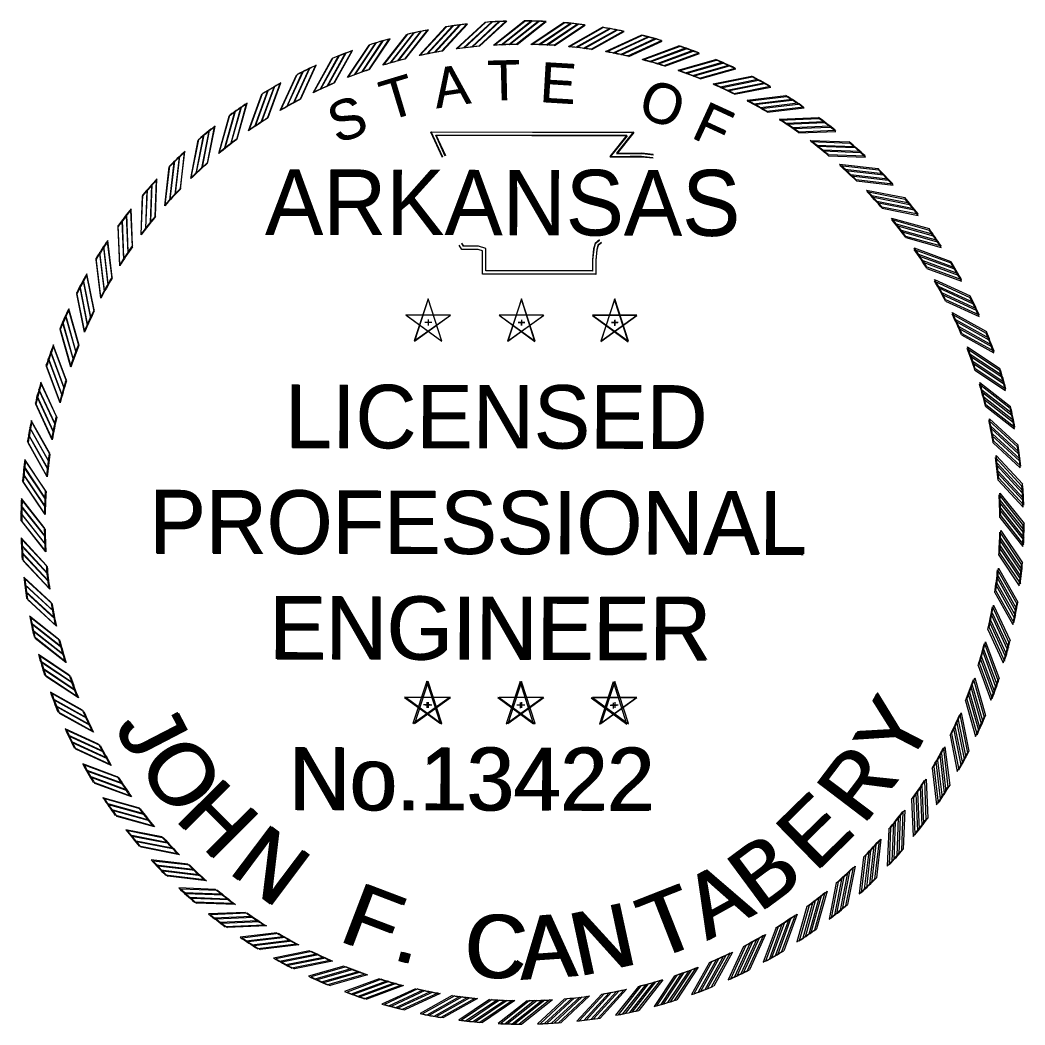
# Model space of a CAD drawing. Extents: x 1448008.9 to 1448047, y 2057056.5 to 2057079.8.
# Drawn here: x 1448044.528 to 1448046.959, y 2057073.225 to 2057075.654 of the extents above; entities that cross this region are included whole.
import ezdxf

# ---------------------------------------------------------------- set-up
doc = ezdxf.new("R2010")
doc.units = 0
doc.layers.add('Default', color=7, linetype='Continuous')

# ---------------------------------------------------------------- blocks, each defined once
blk = doc.blocks.new('STAR')
at = {"layer": 'Default'}
for p, q in [((-0.0001, 0.0615), (-0.0366, -0.0504)), ((0.0362, -0.0503), (0, 0.0617)), ((0.0587, 0.0188), (-0.059, 0.0189)), ((-0.0589, 0.0188), (0.0363, -0.0505)), ((-0.0365, -0.0503), (0.0589, 0.0188)), ((-0.0085, 0), (0.009, 0)), ((0, 0.0063), (0, -0.0085))]:
    blk.add_line(p, q, dxfattribs=at)
blk = doc.blocks.new('RP')
at = {"layer": 'Default'}
for p, q in [((-0.0781, 1.2656), (0.003, 1.33)), ((-0.058, 1.2667), (0.0216, 1.3299)), ((-0.0375, 1.2674), (0.0405, 1.3294)), ((-0.0176, 1.2679), (0.059, 1.3287))]:
    blk.add_line(p, q, dxfattribs=at)
for radius, start, end in [(1.33, 87.4562, 89.8699), (1.268, 90.7933, 93.5307)]:
    blk.add_arc((0, 0), radius, start, end, dxfattribs=at)

msp = doc.modelspace()

# ---------------------------------------------------------------- linework, layer by layer
at = {"layer": 'Default'}
for points in [[(1448045.5496, 2057075.322), (1448045.5213, 2057075.3834), (1448046.0117, 2057075.3837), (1448045.9707, 2057075.3322), (1448046.004, 2057075.3327), (1448046.0319, 2057075.333), (1448046.0597, 2057075.33)], [(1448045.5506, 2057075.3224), (1448045.5225, 2057075.3839), (1448046.0129, 2057075.3825), (1448045.9717, 2057075.3311), (1448046.005, 2057075.3314), (1448046.0329, 2057075.3317), (1448046.0607, 2057075.3286)], [(1448045.5567, 2057075.3253), (1448045.5334, 2057075.3757), (1448045.9956, 2057075.3759), (1448045.9544, 2057075.3243), (1448046.0041, 2057075.3249), (1448046.0315, 2057075.3253), (1448046.0588, 2057075.3223)], [(1448045.5576, 2057075.3256), (1448045.5346, 2057075.3761), (1448045.9967, 2057075.3747), (1448045.9554, 2057075.3232), (1448046.0051, 2057075.3237), (1448046.0325, 2057075.3239), (1448046.0598, 2057075.3209)], [(1448045.9295, 2057075.1226), (1448045.9192, 2057075.1142), (1448045.9156, 2057075.101), (1448045.9127, 2057075.0746), (1448045.9127, 2057075.048), (1448045.6545, 2057075.048), (1448045.6545, 2057075.086), (1448045.6545, 2057075.1019), (1448045.6368, 2057075.1073), (1448045.6009, 2057075.1073), (1448045.5963, 2057075.1144)], [(1448045.9298, 2057075.1216), (1448045.9195, 2057075.1132), (1448045.9158, 2057075.1001), (1448045.9128, 2057075.0736), (1448045.9128, 2057075.0471), (1448045.6545, 2057075.048), (1448045.6547, 2057075.086), (1448045.6547, 2057075.1019), (1448045.637, 2057075.1074), (1448045.6011, 2057075.1075), (1448045.5965, 2057075.1145)], [(1448045.9344, 2057075.1165), (1448045.926, 2057075.1097), (1448045.9233, 2057075.0996), (1448045.9205, 2057075.0741), (1448045.9205, 2057075.0402), (1448045.6467, 2057075.0402), (1448045.6467, 2057075.086), (1448045.6467, 2057075.0962), (1448045.6356, 2057075.0996), (1448045.5967, 2057075.0996), (1448045.5898, 2057075.1101)], [(1448045.9347, 2057075.1155), (1448045.9263, 2057075.1088), (1448045.9235, 2057075.0986), (1448045.9206, 2057075.0732), (1448045.9205, 2057075.0393), (1448045.6467, 2057075.0402), (1448045.6469, 2057075.086), (1448045.6469, 2057075.0962), (1448045.6358, 2057075.0996), (1448045.5969, 2057075.0997), (1448045.59, 2057075.1103)]]:
    msp.add_lwpolyline(points, dxfattribs=at)

# ---------------------------------------------------------------- block references
for name, p, xscale, yscale, rotation in [('RP', (1448045.7444, 2057074.4396), 0.9117655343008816, 0.911765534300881, -4.499999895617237), ('RP', (1448045.7424, 2057074.4393), 0.9117655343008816, 0.9117655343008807, -4.695800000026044), ('RP', (1448045.7444, 2057074.4396), 0.9117655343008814, 0.9117655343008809, 13.500000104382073), ('RP', (1448045.7424, 2057074.4393), 0.9117655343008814, 0.9117655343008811, 13.304199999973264), ('RP', (1448045.7444, 2057074.4396), 0.9117655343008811, 0.9117655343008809, 9.000000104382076), ('RP', (1448045.7424, 2057074.4393), 0.9117655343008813, 0.9117655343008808, 8.804199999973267), ('RP', (1448045.7444, 2057074.4396), 0.9117655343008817, 0.9117655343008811, 4.500000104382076), ('RP', (1448045.7424, 2057074.4393), 0.9117655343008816, 0.9117655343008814, 4.304199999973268), ('RP', (1448045.7444, 2057074.4396), 0.9117655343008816, 0.911765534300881, 1.0438208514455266e-07), ('RP', (1448045.7424, 2057074.4393), 0.9117655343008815, 0.911765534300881, -0.19580000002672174), ('RP', (1448045.7444, 2057074.4396), 0.9117655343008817, 0.9117655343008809, -8.999999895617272), ('RP', (1448045.7424, 2057074.4393), 0.9117655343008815, 0.911765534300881, -9.195800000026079), ('RP', (1448045.7444, 2057074.4396), 0.9117655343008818, 0.9117655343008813, -13.499999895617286), ('RP', (1448045.7424, 2057074.4393), 0.9117655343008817, 0.9117655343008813, -13.695800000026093), ('RP', (1448045.7444, 2057074.4396), 0.9117655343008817, 0.9117655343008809, 18.000000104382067), ('RP', (1448045.7424, 2057074.4393), 0.9117655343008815, 0.9117655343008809, 17.80419999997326), ('RP', (1448045.7444, 2057074.4396), 0.9117655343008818, 0.911765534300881, -17.99999989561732), ('RP', (1448045.7424, 2057074.4393), 0.9117655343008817, 0.911765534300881, -18.19580000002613), ('RP', (1448045.7444, 2057074.4396), 0.9117655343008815, 0.911765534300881, 22.500000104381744), ('RP', (1448045.7424, 2057074.4393), 0.9117655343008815, 0.911765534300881, 22.304199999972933), ('RP', (1448045.7444, 2057074.4396), 0.9117655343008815, 0.9117655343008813, -22.499999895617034), ('RP', (1448045.7424, 2057074.4393), 0.9117655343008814, 0.9117655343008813, -22.695800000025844), ('RP', (1448045.7444, 2057074.4396), 0.9117655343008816, 0.9117655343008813, 27.000000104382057), ('RP', (1448045.7424, 2057074.4393), 0.9117655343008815, 0.9117655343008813, 26.80419999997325), ('RP', (1448045.7444, 2057074.4396), 0.9117655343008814, 0.9117655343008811, -26.999999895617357), ('RP', (1448045.7424, 2057074.4393), 0.9117655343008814, 0.911765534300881, -27.19580000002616), ('RP', (1448045.7444, 2057074.4396), 0.9117655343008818, 0.9117655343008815, -31.49999989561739), ('RP', (1448045.7424, 2057074.4393), 0.9117655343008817, 0.9117655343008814, -31.695800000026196), ('RP', (1448045.7444, 2057074.4396), 0.911765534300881, 0.9117655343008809, 31.500000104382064), ('RP', (1448045.7424, 2057074.4393), 0.9117655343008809, 0.9117655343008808, 31.30419999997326), ('RP', (1448045.7444, 2057074.4396), 0.9117655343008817, 0.9117655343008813, -35.999999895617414), ('RP', (1448045.7424, 2057074.4393), 0.9117655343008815, 0.9117655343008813, -36.195800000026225), ('RP', (1448045.7444, 2057074.4396), 0.9117655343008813, 0.911765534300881, 36.000000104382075), ('RP', (1448045.7424, 2057074.4393), 0.911765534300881, 0.9117655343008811, 35.804199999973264), ('RP', (1448045.7444, 2057074.4396), 0.9117655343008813, 0.911765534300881, 40.50000010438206), ('RP', (1448045.7424, 2057074.4393), 0.9117655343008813, 0.911765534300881, 40.30419999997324), ('RP', (1448045.7444, 2057074.4396), 0.9117655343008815, 0.9117655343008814, -40.49999989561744), ('RP', (1448045.7424, 2057074.4393), 0.9117655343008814, 0.9117655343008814, -40.69580000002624), ('RP', (1448045.7424, 2057074.4393), 0.9117655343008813, 0.911765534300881, 44.80419999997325), ('RP', (1448045.7444, 2057074.4396), 0.9117655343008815, 0.911765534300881, -44.99999989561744), ('RP', (1448045.7424, 2057074.4393), 0.9117655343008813, 0.911765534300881, -45.19580000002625), ('RP', (1448045.7444, 2057074.4396), 0.9117655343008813, 0.9117655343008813, 45.00000010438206), ('RP', (1448045.7444, 2057074.4396), 0.9117655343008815, 0.9117655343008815, 49.500000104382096), ('RP', (1448045.7424, 2057074.4393), 0.9117655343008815, 0.9117655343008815, 49.30419999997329), ('RP', (1448045.7444, 2057074.4396), 0.911765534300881, 0.9117655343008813, -49.499999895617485), ('RP', (1448045.7424, 2057074.4393), 0.911765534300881, 0.911765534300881, -49.69580000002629), ('RP', (1448045.7444, 2057074.4396), 0.9117655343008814, 0.9117655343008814, 54.00000010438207), ('RP', (1448045.7424, 2057074.4393), 0.9117655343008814, 0.9117655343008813, 53.804199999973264), ('RP', (1448045.7444, 2057074.4396), 0.9117655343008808, 0.9117655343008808, -53.999999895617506), ('RP', (1448045.7424, 2057074.4393), 0.9117655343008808, 0.9117655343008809, -54.1958000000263), ('RP', (1448045.7424, 2057074.4393), 0.9117655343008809, 0.9117655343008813, 58.304199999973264), ('RP', (1448045.7444, 2057074.4396), 0.911765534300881, 0.9117655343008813, 58.50000010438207), ('RP', (1448045.7444, 2057074.4396), 0.911765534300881, 0.9117655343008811, -58.49999989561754), ('RP', (1448045.7424, 2057074.4393), 0.9117655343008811, 0.9117655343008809, -58.695800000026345), ('RP', (1448045.7444, 2057074.4396), 0.911765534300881, 0.9117655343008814, -62.99999989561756), ('RP', (1448045.7424, 2057074.4393), 0.9117655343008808, 0.9117655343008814, -63.19580000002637), ('RP', (1448045.7424, 2057074.4393), 0.9117655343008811, 0.9117655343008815, 62.804199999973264), ('RP', (1448045.7444, 2057074.4396), 0.9117655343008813, 0.9117655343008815, 63.000000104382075), ('STAR', (1448045.5151, 2057074.9242), 0.9117655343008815, 0.911765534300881, -0.19580000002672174), ('STAR', (1448045.5155, 2057074.9238), 0.9117655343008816, 0.911765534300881, 1.0438208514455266e-07), ('STAR', (1448045.7406, 2057074.9234), 0.9117655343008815, 0.911765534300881, -0.19580000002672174), ('STAR', (1448045.741, 2057074.9238), 0.9117655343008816, 0.911765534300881, 1.0438208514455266e-07), ('STAR', (1448045.9662, 2057074.9227), 0.9117655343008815, 0.911765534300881, -0.19580000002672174), ('STAR', (1448045.9666, 2057074.9238), 0.9117655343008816, 0.911765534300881, 1.0438208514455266e-07), ('RP', (1448045.7424, 2057074.4393), 0.911765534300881, 0.9117655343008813, 67.30419999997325), ('RP', (1448045.7444, 2057074.4396), 0.911765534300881, 0.9117655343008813, 67.50000010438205), ('RP', (1448045.7424, 2057074.4393), 0.9117655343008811, 0.9117655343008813, -67.69580000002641), ('RP', (1448045.7444, 2057074.4396), 0.911765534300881, 0.9117655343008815, -67.49999989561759), ('RP', (1448045.7424, 2057074.4393), 0.911765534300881, 0.9117655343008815, -72.19580000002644), ('RP', (1448045.7444, 2057074.4396), 0.9117655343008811, 0.9117655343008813, -71.99999989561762), ('RP', (1448045.7424, 2057074.4393), 0.9117655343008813, 0.9117655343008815, 71.80419999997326), ('RP', (1448045.7444, 2057074.4396), 0.9117655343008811, 0.9117655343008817, 72.00000010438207), ('RP', (1448045.7424, 2057074.4393), 0.911765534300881, 0.9117655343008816, 76.30419999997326), ('RP', (1448045.7424, 2057074.4393), 0.9117655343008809, 0.911765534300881, -76.69580000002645), ('RP', (1448045.7444, 2057074.4396), 0.9117655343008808, 0.9117655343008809, -76.49999989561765), ('RP', (1448045.7444, 2057074.4396), 0.9117655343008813, 0.9117655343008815, 76.50000010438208), ('RP', (1448045.7424, 2057074.4393), 0.9117655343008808, 0.9117655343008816, 80.80419999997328), ('RP', (1448045.7444, 2057074.4396), 0.9117655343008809, 0.9117655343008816, 81.0000001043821), ('RP', (1448045.7424, 2057074.4393), 0.911765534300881, 0.9117655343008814, -81.19580000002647), ('RP', (1448045.7444, 2057074.4396), 0.9117655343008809, 0.9117655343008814, -80.99999989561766), ('RP', (1448045.7424, 2057074.4393), 0.9117655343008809, 0.9117655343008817, 85.30419999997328), ('RP', (1448045.7444, 2057074.4396), 0.9117655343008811, 0.9117655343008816, 85.50000010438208), ('RP', (1448045.7424, 2057074.4393), 0.9117655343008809, 0.9117655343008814, -85.69580000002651), ('RP', (1448045.7444, 2057074.4396), 0.9117655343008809, 0.9117655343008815, -85.49999989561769), ('RP', (1448045.7424, 2057074.4393), 0.911765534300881, 0.9117655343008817, 89.80419999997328), ('RP', (1448045.7444, 2057074.4396), 0.9117655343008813, 0.9117655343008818, 90.0000001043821), ('RP', (1448045.7424, 2057074.4393), 0.9117655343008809, 0.9117655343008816, -90.19580000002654), ('RP', (1448045.7444, 2057074.4396), 0.911765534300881, 0.9117655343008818, -89.99999989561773), ('RP', (1448045.7424, 2057074.4393), 0.911765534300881, 0.9117655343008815, -94.69580000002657), ('RP', (1448045.7444, 2057074.4396), 0.9117655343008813, 0.9117655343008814, -94.49999989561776), ('RP', (1448045.7424, 2057074.4393), 0.911765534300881, 0.9117655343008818, 94.30419999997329), ('RP', (1448045.7444, 2057074.4396), 0.9117655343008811, 0.9117655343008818, 94.5000001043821), ('RP', (1448045.7424, 2057074.4393), 0.911765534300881, 0.9117655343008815, -99.19580000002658), ('RP', (1448045.7444, 2057074.4396), 0.9117655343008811, 0.9117655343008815, -98.99999989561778), ('RP', (1448045.7424, 2057074.4393), 0.9117655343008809, 0.9117655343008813, 98.8041999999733), ('RP', (1448045.7444, 2057074.4396), 0.9117655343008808, 0.9117655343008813, 99.0000001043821), ('RP', (1448045.7424, 2057074.4393), 0.911765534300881, 0.9117655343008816, 103.30419999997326), ('RP', (1448045.7444, 2057074.4396), 0.911765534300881, 0.9117655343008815, 103.50000010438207), ('RP', (1448045.7424, 2057074.4393), 0.9117655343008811, 0.9117655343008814, -103.69580000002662), ('RP', (1448045.7444, 2057074.4396), 0.911765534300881, 0.9117655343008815, -103.49999989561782), ('RP', (1448045.7424, 2057074.4393), 0.9117655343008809, 0.9117655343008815, -108.19580000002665), ('RP', (1448045.7444, 2057074.4396), 0.9117655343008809, 0.9117655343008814, -107.99999989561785), ('RP', (1448045.7424, 2057074.4393), 0.9117655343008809, 0.9117655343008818, 107.80419999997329), ('RP', (1448045.7444, 2057074.4396), 0.9117655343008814, 0.9117655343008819, 108.0000001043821), ('RP', (1448045.7424, 2057074.4393), 0.911765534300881, 0.9117655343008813, 112.30419999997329), ('STAR', (1448045.5119, 2057073.9994), 0.9117655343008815, 0.911765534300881, -0.19580000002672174), ('STAR', (1448045.5155, 2057073.999), 0.9117655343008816, 0.911765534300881, 1.0438208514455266e-07), ('STAR', (1448045.7375, 2057073.9987), 0.9117655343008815, 0.911765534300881, -0.19580000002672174), ('STAR', (1448045.741, 2057073.999), 0.9117655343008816, 0.911765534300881, 1.0438208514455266e-07), ('STAR', (1448045.963, 2057073.9979), 0.9117655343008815, 0.911765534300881, -0.19580000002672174), ('STAR', (1448045.9666, 2057073.999), 0.9117655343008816, 0.911765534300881, 1.0438208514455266e-07), ('RP', (1448045.7424, 2057074.4393), 0.9117655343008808, 0.9117655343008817, -112.69580000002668), ('RP', (1448045.7444, 2057074.4396), 0.9117655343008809, 0.9117655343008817, -112.49999989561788), ('RP', (1448045.7444, 2057074.4396), 0.9117655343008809, 0.9117655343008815, 112.5000001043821), ('RP', (1448045.7444, 2057074.4396), 0.9117655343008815, 0.9117655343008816, -116.9999998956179), ('RP', (1448045.7424, 2057074.4393), 0.9117655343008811, 0.9117655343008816, 116.80419999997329), ('RP', (1448045.7444, 2057074.4396), 0.9117655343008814, 0.9117655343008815, 117.0000001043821), ('RP', (1448045.7424, 2057074.4393), 0.9117655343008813, 0.9117655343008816, -117.19580000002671), ('RP', (1448045.7424, 2057074.4393), 0.9117655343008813, 0.9117655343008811, 121.30419999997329), ('RP', (1448045.7444, 2057074.4396), 0.9117655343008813, 0.9117655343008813, 121.5000001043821), ('RP', (1448045.7424, 2057074.4393), 0.9117655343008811, 0.9117655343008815, -121.69580000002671), ('RP', (1448045.7444, 2057074.4396), 0.9117655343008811, 0.9117655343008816, -121.4999998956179), ('RP', (1448045.7424, 2057074.4393), 0.911765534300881, 0.911765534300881, 125.80419999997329), ('RP', (1448045.7424, 2057074.4393), 0.9117655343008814, 0.9117655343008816, -126.19580000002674), ('RP', (1448045.7444, 2057074.4396), 0.9117655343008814, 0.9117655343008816, -125.99999989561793), ('RP', (1448045.7444, 2057074.4396), 0.911765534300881, 0.9117655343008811, 126.00000010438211), ('RP', (1448045.7424, 2057074.4393), 0.9117655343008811, 0.9117655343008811, 130.3041999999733), ('RP', (1448045.7424, 2057074.4393), 0.9117655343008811, 0.9117655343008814, -130.6958000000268), ('RP', (1448045.7444, 2057074.4396), 0.9117655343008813, 0.9117655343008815, -130.49999989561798), ('RP', (1448045.7444, 2057074.4396), 0.911765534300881, 0.9117655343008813, 130.50000010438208), ('RP', (1448045.7424, 2057074.4393), 0.9117655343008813, 0.911765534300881, 134.80419999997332), ('RP', (1448045.7444, 2057074.4396), 0.9117655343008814, 0.9117655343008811, 135.00000010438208), ('RP', (1448045.7424, 2057074.4393), 0.9117655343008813, 0.911765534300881, -135.19580000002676), ('RP', (1448045.7444, 2057074.4396), 0.9117655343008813, 0.9117655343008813, -134.99999989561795), ('RP', (1448045.7424, 2057074.4393), 0.9117655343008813, 0.9117655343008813, 139.30419999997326), ('RP', (1448045.7444, 2057074.4396), 0.9117655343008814, 0.9117655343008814, 139.50000010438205), ('RP', (1448045.7424, 2057074.4393), 0.9117655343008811, 0.9117655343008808, -139.69580000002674), ('RP', (1448045.7444, 2057074.4396), 0.911765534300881, 0.911765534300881, -139.49999989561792), ('RP', (1448045.7424, 2057074.4393), 0.9117655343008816, 0.9117655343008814, 143.8041999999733), ('RP', (1448045.7424, 2057074.4393), 0.9117655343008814, 0.9117655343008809, -144.19580000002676), ('RP', (1448045.7444, 2057074.4396), 0.9117655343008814, 0.9117655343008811, -143.99999989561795), ('RP', (1448045.7444, 2057074.4396), 0.9117655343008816, 0.9117655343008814, 144.00000010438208), ('RP', (1448045.7424, 2057074.4393), 0.9117655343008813, 0.9117655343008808, -148.69580000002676), ('RP', (1448045.7444, 2057074.4396), 0.911765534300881, 0.911765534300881, -148.49999989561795), ('RP', (1448045.7424, 2057074.4393), 0.9117655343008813, 0.9117655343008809, 148.3041999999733), ('RP', (1448045.7444, 2057074.4396), 0.9117655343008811, 0.9117655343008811, 148.50000010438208), ('RP', (1448045.7424, 2057074.4393), 0.9117655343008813, 0.9117655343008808, -153.1958000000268), ('RP', (1448045.7444, 2057074.4396), 0.9117655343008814, 0.9117655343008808, -152.99999989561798), ('RP', (1448045.7424, 2057074.4393), 0.9117655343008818, 0.9117655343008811, 152.8041999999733), ('RP', (1448045.7444, 2057074.4396), 0.9117655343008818, 0.9117655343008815, 153.00000010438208), ('RP', (1448045.7424, 2057074.4393), 0.9117655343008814, 0.9117655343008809, 157.3041999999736), ('RP', (1448045.7444, 2057074.4396), 0.9117655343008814, 0.911765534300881, 157.50000010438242), ('RP', (1448045.7424, 2057074.4393), 0.9117655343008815, 0.9117655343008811, -157.6958000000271), ('RP', (1448045.7444, 2057074.4396), 0.9117655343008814, 0.9117655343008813, -157.4999998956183), ('RP', (1448045.7424, 2057074.4393), 0.9117655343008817, 0.911765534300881, 161.8041999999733), ('RP', (1448045.7444, 2057074.4396), 0.9117655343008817, 0.9117655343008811, 162.00000010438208), ('RP', (1448045.7424, 2057074.4393), 0.9117655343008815, 0.9117655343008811, -162.19580000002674), ('RP', (1448045.7444, 2057074.4396), 0.9117655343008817, 0.911765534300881, -161.99999989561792), ('RP', (1448045.7424, 2057074.4393), 0.9117655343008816, 0.9117655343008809, 166.3041999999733), ('RP', (1448045.7444, 2057074.4396), 0.9117655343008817, 0.9117655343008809, 166.50000010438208), ('RP', (1448045.7424, 2057074.4393), 0.9117655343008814, 0.9117655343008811, -166.69580000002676), ('RP', (1448045.7444, 2057074.4396), 0.9117655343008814, 0.9117655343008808, -166.49999989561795), ('RP', (1448045.7424, 2057074.4393), 0.9117655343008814, 0.9117655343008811, 170.8041999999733), ('RP', (1448045.7444, 2057074.4396), 0.9117655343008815, 0.911765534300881, 171.00000010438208), ('RP', (1448045.7424, 2057074.4393), 0.911765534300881, 0.911765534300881, -171.19580000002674), ('RP', (1448045.7444, 2057074.4396), 0.9117655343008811, 0.9117655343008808, -170.99999989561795), ('RP', (1448045.7424, 2057074.4393), 0.9117655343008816, 0.911765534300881, 175.3041999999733), ('RP', (1448045.7444, 2057074.4396), 0.9117655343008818, 0.911765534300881, 175.50000010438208), ('RP', (1448045.7424, 2057074.4393), 0.9117655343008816, 0.9117655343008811, 179.8041999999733), ('RP', (1448045.7444, 2057074.4396), 0.9117655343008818, 0.9117655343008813, -179.99999989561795), ('RP', (1448045.7424, 2057074.4393), 0.9117655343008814, 0.911765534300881, -175.69580000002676), ('RP', (1448045.7444, 2057074.4396), 0.9117655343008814, 0.9117655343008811, -175.49999989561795)]:
    msp.add_blockref(name, p, dxfattribs=dict(at, xscale=xscale, yscale=yscale, rotation=rotation))

# ---------------------------------------------------------------- texts
for s, height, rotation, p in [('T', 0.0967, 1.4789, (1448045.6596, 2057075.4594)), ('T', 0.0967, 1.2831, (1448045.661, 2057075.4593)), ('A', 0.0967, 8.6788, (1448045.5347, 2057075.4401)), ('A', 0.0967, 8.483, (1448045.536, 2057075.4405)), ('E', 0.0967, 356.672, (1448045.7834, 2057075.4564)), ('E', 0.0967, 356.4762, (1448045.7848, 2057075.4559)), ('T', 0.0967, 16.9015, (1448045.4172, 2057075.4094)), ('T', 0.0967, 16.7057, (1448045.4185, 2057075.4102)), ('O', 0.0967, 341.2218, (1448046.0183, 2057075.4232)), ('O', 0.0967, 341.026, (1448046.0196, 2057075.422)), ('S', 0.0967, 19.7726, (1448045.2942, 2057075.3542)), ('S', 0.0967, 19.5768, (1448045.2953, 2057075.3554)), ('F', 0.0967, 335.3628, (1448046.1487, 2057075.3723)), ('F', 0.0967, 335.167, (1448046.1498, 2057075.3705)), ('ARKANSAS', 0.15788, 0, (1448045.1204, 2057075.1342)), ('ARKANSAS', 0.15788, 359.8042, (1448045.1207, 2057075.136)), ('LICENSED', 0.15285, 359.8042, (1448045.168, 2057074.6204)), ('LICENSED', 0.15285, 0, (1448045.1694, 2057074.6188)), ('PROFESSIONAL', 0.152848, 359.8042, (1448044.8396, 2057074.3659)), ('PROFESSIONAL', 0.152848, 0, (1448044.8419, 2057074.3632)), ('ENGINEER', 0.15285, 359.8042, (1448045.1298, 2057074.1093)), ('ENGINEER', 0.15285, 0, (1448045.133, 2057074.1076)), ('Y', 0.1528, 62.5392, (1448046.6741, 2057073.8394)), ('Y', 0.1528, 62.735, (1448046.6782, 2057073.8429)), ('J', 0.1528, 297.2813, (1448044.7544, 2057073.948)), ('J', 0.1528, 297.4771, (1448044.7581, 2057073.945)), ('O', 0.1528, 304.1899, (1448044.8085, 2057073.8543)), ('O', 0.1528, 304.3857, (1448044.8126, 2057073.8514)), ('No.13422', 0.15225, 359.8042, (1448045.1768, 2057073.7448)), ('No.13422', 0.15225, 0, (1448045.1813, 2057073.7432)), ('R', 0.1528, 52.7437, (1448046.5674, 2057073.7048)), ('R', 0.1528, 52.9395, (1448046.572, 2057073.708)), ('H', 0.1528, 314.7447, (1448044.8987, 2057073.7226)), ('H', 0.1528, 314.9405, (1448044.9032, 2057073.72)), ('E', 0.1528, 44.306, (1448046.451, 2057073.5911)), ('E', 0.1528, 44.5018, (1448046.4559, 2057073.5938)), ('N', 0.1528, 322.9417, (1448045.0277, 2057073.5948)), ('N', 0.1528, 323.1375, (1448045.0327, 2057073.5927)), ('B', 0.1528, 36.505, (1448046.3161, 2057073.4938)), ('B', 0.1528, 36.7008, (1448046.3214, 2057073.4961)), ('A', 0.1528, 28.8562, (1448046.1891, 2057073.4271)), ('A', 0.1528, 29.052, (1448046.1946, 2057073.429)), ('F', 0.1528, 339.0288, (1448045.2945, 2057073.4293)), ('F', 0.1528, 339.2246, (1448045.3, 2057073.4281)), ('T', 0.1528, 21.4329, (1448046.0621, 2057073.3793)), ('T', 0.1528, 21.6287, (1448046.0677, 2057073.3807)), ('N', 0.1528, 12.0703, (1448045.8777, 2057073.3412)), ('N', 0.1528, 12.2661, (1448045.8835, 2057073.342)), ('C', 0.1528, 356.1028, (1448045.5978, 2057073.3435)), ('C', 0.1528, 356.2986, (1448045.6036, 2057073.3433)), ('A', 0.1528, 3.9092, (1448045.738, 2057073.3333)), ('A', 0.1528, 4.105, (1448045.7438, 2057073.3337)), ('.', 0.1528, 344.7037, (1448045.4249, 2057073.3841)), ('.', 0.1528, 344.8995, (1448045.4306, 2057073.3833))]:
    msp.add_text(s, height=height, rotation=rotation, dxfattribs=at).set_placement(p)

doc.saveas('drawing.dxf')
